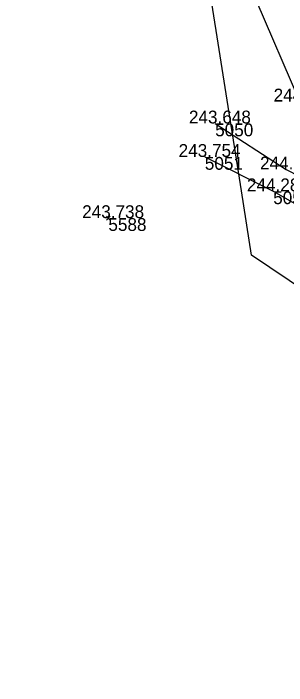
# Model space of a CAD drawing. Extents: x -809970 to -809480, y -1011362 to -1010672.
# Drawn here: x -809887.1 to -809861.5, y -1011032.7 to -1010969.8 of the extents above; entities that cross this region are included whole.
import ezdxf

# ---------------------------------------------------------------- set-up
doc = ezdxf.new("R2010")
doc.units = 0
for name, color, linetype in [('Vrstva 49', 7, 'Continuous'), ('Vrstva 51', 7, 'Continuous'), ('Vrstva 53', 7, 'Continuous'), ('Vrstva 60', 7, 'Continuous'), ('Vrstva 61', 7, 'Continuous')]:
    doc.layers.add(name, color=color, linetype=linetype)

msp = doc.modelspace()

# ---------------------------------------------------------------- linework, layer by layer
at = {"layer": 'Vrstva 49'}
for p, q in [((-809878.349, -1010988.806), (-809877.995, -1010989.16)), ((-809878.349, -1010989.16), (-809877.995, -1010988.806))]:
    msp.add_line(p, q, dxfattribs=at)
msp.add_lwpolyline([(-809846.733, -1010986.717), (-809852.633, -1010985.242), (-809855.833, -1010983.597), (-809858.12, -1010981.877), (-809860.248, -1010978.081), (-809864.337, -1010968.616), (-809864.72, -1010965.088), (-809878.39, -1010927.249), (-809884.518, -1010905.485), (-809883.3, -1010886.554), (-809883.077, -1010886.562), (-809880.73, -1010884.265), (-809876.323, -1010881.843), (-809865.405, -1010877.268)], dxfattribs=at)
at = {"layer": 'Vrstva 51'}
for points in [[(-809868.177, -1010980.133), (-809861.522, -1010984.435), (-809856.273, -1010987.12), (-809851.693, -1010988.364), (-809846.095, -1010987.906), (-809837.047, -1010985.065), (-809827.686, -1010983.646), (-809817.51, -1010983.979), (-809809.643, -1010984.731), (-809805.029, -1010984.43)], [(-809869.144, -1010983.263), (-809862.744, -1010986.475), (-809856.658, -1010989.933), (-809852.549, -1010991.524), (-809844.992, -1010990.276), (-809835.966, -1010987.57), (-809827.372, -1010986.165), (-809817.539, -1010986.227), (-809810.453, -1010986.917), (-809804.657, -1010986.868)]]:
    msp.add_lwpolyline(points, dxfattribs=at)
at = {"layer": 'Vrstva 53'}
msp.add_lwpolyline([(-809810.89, -1011076.81), (-809836.26, -1011028.53), (-809850.32, -1011003.33), (-809854.51, -1011000.24), (-809856.34, -1010998.68), (-809859.52, -1010995.97), (-809864.77, -1010992.44), (-809865.72, -1010986.44), (-809870.58, -1010955.65), (-809883.99, -1010901.78), (-809890.33, -1010872.36), (-809892.39, -1010868.68), (-809893.92, -1010865.41), (-809894.78, -1010861.65), (-809898.21, -1010828.41), (-809898.47, -1010814.6), (-809887.66, -1010796.86), (-809893.8, -1010725.05), (-809890.92, -1010677.02)], dxfattribs=at)
at = {"layer": 'Vrstva 60'}
for p, q in [((-809868.177, -1010980.133), (-809868.177, -1010980.133)), ((-809869.144, -1010983.263), (-809869.144, -1010983.263)), ((-809861.522, -1010984.435), (-809861.522, -1010984.435)), ((-809862.744, -1010986.475), (-809862.744, -1010986.475)), ((-809878.172, -1010988.983), (-809878.172, -1010988.983))]:
    msp.add_line(p, q, dxfattribs=at)

# ---------------------------------------------------------------- texts
for s, p in [('5050', (-809868.177, -1010981.333)), ('5051', (-809869.144, -1010984.463)), ('5052', (-809862.744, -1010987.675)), ('5588', (-809878.172, -1010990.183))]:
    msp.add_text(s, height=1.2, dxfattribs=at).set_placement(p)
at = {"layer": 'Vrstva 61'}
for s, p in [('244.308', (-809862.702, -1010978.081)), ('243.648', (-809870.631, -1010980.133)), ('243.754', (-809871.595, -1010983.263)), ('244.228', (-809863.976, -1010984.435)), ('244.285', (-809865.2, -1010986.475)), ('243.738', (-809880.626, -1010988.983))]:
    msp.add_text(s, height=1.2, dxfattribs=at).set_placement(p)

doc.saveas('drawing.dxf')
